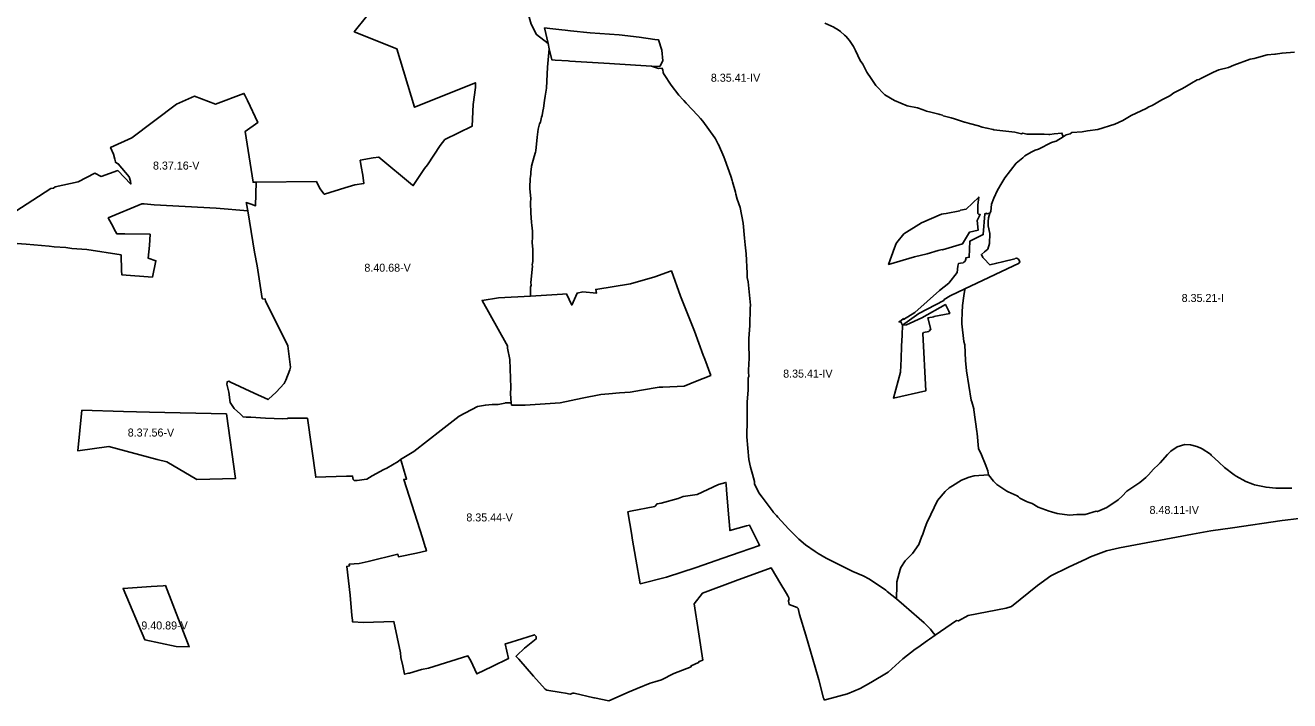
# Model space of a CAD drawing. Extents: x -444937 to -440470, y -1149084 to -1129741.
# Drawn here: x -443286 to -441707, y -1132883 to -1132039 of the extents above; entities that cross this region are included whole.
import ezdxf

# ---------------------------------------------------------------- set-up
doc = ezdxf.new("R2010")
doc.units = 0
doc.layers.add('Vrstva 28', color=7, linetype='Continuous')

msp = doc.modelspace()

# ---------------------------------------------------------------- linework, layer by layer
at = {"layer": 'Vrstva 28'}
for points in [[(-442663.04, -1132002.17), (-442658.9, -1132020.83), (-442654.27, -1132037.04), (-442647.66, -1132050.27), (-442633.17, -1132061.48)], [(-442998.03, -1132234.73), (-442922.59, -1132233.93), (-442918.4, -1132242.63), (-442912.99, -1132249.51), (-442912.72, -1132249.43), (-442887.05, -1132241.64), (-442874.77, -1132237.91), (-442863.26, -1132236.08), (-442864.88, -1132225.96), (-442866.63, -1132214.97), (-442867.88, -1132207.12), (-442851.91, -1132204.38), (-442844.71, -1132203.15), (-442802.61, -1132238.12), (-442801.77, -1132238.8), (-442787.72, -1132217.54), (-442783.89, -1132212.86), (-442767.92, -1132188.8), (-442762.18, -1132181.35), (-442727.93, -1132164.44), (-442726.84, -1132137.72), (-442724.07, -1132116.43), (-442724.07, -1132110.89), (-442724.04, -1132110.37), (-442800.21, -1132140.96), (-442822.05, -1132068.1), (-442875.47, -1132046.72), (-442860.07, -1132027.41)], [(-441989.7, -1132178.08), (-441991.21, -1132173.35), (-442001.18, -1132174.32), (-442006.51, -1132174.84), (-442007.71, -1132174.82), (-442013.34, -1132174.74), (-442019.94, -1132174.64), (-442034.98, -1132174.41), (-442040.09, -1132173.56), (-442041.79, -1132173.99), (-442050.29, -1132172.07), (-442076.22, -1132169.1), (-442077.21, -1132168.87), (-442084.99, -1132167.09), (-442091.1, -1132165.7), (-442095.35, -1132164), (-442106.74, -1132161.08), (-442112.78, -1132159.53), (-442112.89, -1132159.5), (-442119.3, -1132157.41), (-442125.37, -1132155.44), (-442129.78, -1132154.01), (-442139.56, -1132151.88), (-442139.71, -1132151.73), (-442140.41, -1132151.03), (-442143.81, -1132149.97), (-442144.91, -1132149.7), (-442154.88, -1132147.27), (-442160.39, -1132145.93), (-442164.78, -1132144.39), (-442171.86, -1132141.89), (-442184.61, -1132139.13), (-442200.34, -1132132.54), (-442212.67, -1132125.53), (-442223.93, -1132113.84), (-442229.73, -1132105.19), (-442235.2, -1132097.05), (-442240.09, -1132087.27), (-442243.28, -1132082.6), (-442249.2, -1132070.14), (-442250.91, -1132066.54), (-442251.56, -1132065.17), (-442256.66, -1132057.52), (-442261.13, -1132052.2), (-442262.73, -1132050.8), (-442267.93, -1132046.25), (-442270.93, -1132044.31), (-442275.79, -1132041.15), (-442276.39, -1132040.9), (-442287.7, -1132036.05)], [(-442633.17, -1132061.48), (-442637.57, -1132041.89), (-442631.25, -1132042.56), (-442615.94, -1132044.17), (-442612.11, -1132044.57), (-442605.25, -1132045.29), (-442580.6, -1132047.89), (-442544.42, -1132050.65), (-442519.3, -1132053.43), (-442500, -1132056.18), (-442495.39, -1132056.67), (-442491.09, -1132069.84), (-442490.03, -1132083.02), (-442493.22, -1132089.4), (-442493.79, -1132090.23), (-442503.89, -1132089.6)], [(-442631.7, -1132068.05), (-442633.8, -1132091.01), (-442635.31, -1132117.17), (-442636.82, -1132127.28), (-442637.6, -1132132.55), (-442639, -1132141.92), (-442639.77, -1132145.76), (-442640.85, -1132151.08), (-442641.33, -1132153.43), (-442642.55, -1132159.43), (-442644.04, -1132161.56), (-442645.53, -1132168.37), (-442646.7, -1132178.38), (-442648.72, -1132195.61), (-442649.14, -1132197.15), (-442650.65, -1132202.7), (-442653.85, -1132214.49), (-442654.04, -1132215.2), (-442654.62, -1132222.14), (-442654.79, -1132224.19), (-442655.11, -1132227.97), (-442655.75, -1132229.67), (-442656.14, -1132241.49), (-442656.17, -1132242.44), (-442654.89, -1132255.22), (-442655.32, -1132259.47), (-442655.3, -1132259.89), (-442654.63, -1132273.26), (-442654.35, -1132278.9), (-442654.04, -1132285.02), (-442653.56, -1132288.49), (-442652.55, -1132295.66), (-442652.78, -1132303.29), (-442652.98, -1132310.13), (-442652.22, -1132318.53), (-442652.13, -1132319.5), (-442652.34, -1132333.55), (-442652.98, -1132337.81), (-442652.55, -1132339.51), (-442654.89, -1132359.94), (-442654.47, -1132363.35), (-442655.11, -1132365.9), (-442655.05, -1132374.2), (-442655.03, -1132376.85)], [(-442631.7, -1132068.05), (-442633.17, -1132061.48)], [(-442550.17, -1132086.71), (-442556.66, -1132086.31), (-442606.22, -1132083.21), (-442608.28, -1132083.01), (-442624.45, -1132081.95), (-442624.57, -1132081.94), (-442628.65, -1132081.67), (-442631.33, -1132069.69), (-442631.7, -1132068.05)], [(-442503.89, -1132089.6), (-442550.17, -1132086.71)], [(-441989.7, -1132178.08), (-441986.1, -1132175.26), (-441981, -1132173.99), (-441978.88, -1132172.71), (-441966.13, -1132171.65), (-441959.43, -1132170.63), (-441946.57, -1132168.67), (-441925.32, -1132162.08), (-441915.12, -1132157.62), (-441904.92, -1132151.46), (-441886.15, -1132142.44), (-441882.81, -1132140.41), (-441878.56, -1132138.92), (-441866.66, -1132131.69), (-441856.46, -1132126.59), (-441851.36, -1132122.98), (-441850.48, -1132122.53), (-441841.53, -1132117.91), (-441837.75, -1132115.96), (-441829.47, -1132111.02), (-441822.45, -1132106.82), (-441819.9, -1132106.19), (-441818.59, -1132105.53), (-441802.05, -1132097.26), (-441801.87, -1132097.18), (-441795.25, -1132094.29), (-441783.35, -1132091.1), (-441776.47, -1132088.52), (-441756.14, -1132080.9), (-441751.04, -1132080.05), (-441748.41, -1132079.28), (-441734.89, -1132075.37), (-441725.47, -1132074.78), (-441724.69, -1132074.73), (-441716.18, -1132073.25), (-441700.78, -1132072.28)], [(-442197.83, -1132755.26), (-442209.51, -1132745.94), (-442211.39, -1132744.43), (-442231.59, -1132730.83), (-442239.45, -1132726.58), (-442252.63, -1132721), (-442256.03, -1132719.57), (-442285.78, -1132704.27), (-442295.98, -1132698.53), (-442299.44, -1132696.19), (-442311.71, -1132687.9), (-442320, -1132680.67), (-442325.01, -1132675.66), (-442332.96, -1132667.71), (-442346.21, -1132653.14), (-442348.08, -1132651.08), (-442351.65, -1132647.16), (-442352.09, -1132646.67), (-442365.97, -1132628.22), (-442370.16, -1132622.65), (-442375.26, -1132611.39), (-442375.47, -1132608.41), (-442377.98, -1132599.64), (-442380.57, -1132590.56), (-442382.49, -1132581.21), (-442384.82, -1132552.94), (-442384.62, -1132531.64), (-442384.57, -1132527), (-442384.42, -1132511.28), (-442384.4, -1132508.94), (-442383.34, -1132494.49), (-442383.34, -1132493.39), (-442383.34, -1132479.19), (-442383.23, -1132478.99), (-442382.49, -1132477.49), (-442382.91, -1132471.54), (-442382.34, -1132459.99), (-442382.17, -1132456.43), (-442381.85, -1132449.86), (-442382.49, -1132441.36), (-442382.27, -1132429.88), (-442381.3, -1132413.72), (-442380.68, -1132391.93), (-442380.57, -1132388.22), (-442383.34, -1132359.32), (-442384.4, -1132353.58), (-442384.66, -1132348.37), (-442385.89, -1132324.04), (-442386.94, -1132312.88), (-442387.71, -1132304.72), (-442389.5, -1132285.78), (-442393.32, -1132266.23), (-442396.94, -1132255.81), (-442398.57, -1132249.67), (-442399.32, -1132246.87), (-442402.74, -1132233.99), (-442403.1, -1132232.65), (-442405.15, -1132226.96), (-442412.58, -1132206.29), (-442413.73, -1132203.1), (-442420.32, -1132187.59), (-442420.59, -1132187.06), (-442423.61, -1132181.32), (-442424, -1132180.57), (-442424.78, -1132179.09), (-442439.87, -1132158.26), (-442442.79, -1132155.12), (-442446.37, -1132151.25), (-442460.6, -1132135.91), (-442463.6, -1132132.68), (-442464.46, -1132131.75), (-442469.84, -1132125.95), (-442479.62, -1132113.41), (-442488.33, -1132100.02), (-442489.39, -1132097.9), (-442490.03, -1132093.65), (-442491.09, -1132092.8), (-442490.67, -1132092.16), (-442495.43, -1132092.59), (-442503.89, -1132089.6)], [(-443306.47, -1132276.08), (-443254.53, -1132242.66), (-443251.08, -1132241.87), (-443248.93, -1132240.39), (-443220.48, -1132234.33), (-443199.49, -1132223.43), (-443191.66, -1132227.44), (-443170.95, -1132220.13), (-443154.66, -1132237.05), (-443155.12, -1132233.5), (-443156.48, -1132228.09), (-443170.32, -1132211.47), (-443170.87, -1132211.58), (-443173.77, -1132209.74), (-443173.84, -1132209.35), (-443174.49, -1132205.83), (-443176.37, -1132199.56), (-443179.84, -1132191.22), (-443153.2, -1132179.22), (-443097.29, -1132137.11), (-443075.14, -1132127.27), (-443048.69, -1132137.11), (-443013.18, -1132123.63), (-443012.08, -1132125.93), (-443008.86, -1132132.65)], [(-443008.86, -1132132.65), (-442995.8, -1132159.87), (-443011.58, -1132171.26), (-443001.87, -1132234.77), (-442998.03, -1132234.73)], [(-442081.7, -1132273.49), (-442080.99, -1132272.52), (-442080.05, -1132271.33), (-442079.2, -1132262.19), (-442076.43, -1132254.54), (-442071.76, -1132244.76), (-442066.35, -1132235.45), (-442062.62, -1132229.03), (-442048.59, -1132210.97), (-442040.34, -1132204.15), (-442037.54, -1132201.83), (-442029.89, -1132197.15), (-442024.79, -1132194.6), (-442020.54, -1132193.33), (-442004.38, -1132185.04), (-442003.24, -1132184.71), (-441998.43, -1132183.34), (-441989.7, -1132178.08)], [(-442998.03, -1132234.73), (-442998.63, -1132263.95), (-443004.32, -1132262.08), (-443010.39, -1132260.09), (-443010.04, -1132261.83), (-443008.35, -1132270.24)], [(-442145.93, -1132320), (-442159.54, -1132324.25), (-442175.69, -1132328.08), (-442207.83, -1132337.32), (-442200.33, -1132316.57), (-442198.44, -1132311.31), (-442197.5, -1132310.13), (-442188.9, -1132299.28), (-442166.69, -1132285.36), (-442141.8, -1132274.69), (-442139.09, -1132274.11), (-442135.73, -1132273.67), (-442118.94, -1132270.48), (-442118.14, -1132269.64), (-442110.98, -1132268.11), (-442095.21, -1132253.18), (-442096.41, -1132262.83), (-442096.27, -1132270.13), (-442096.2, -1132273.88), (-442095.14, -1132274.94), (-442093.32, -1132275.06), (-442097.06, -1132282.55), (-442095.83, -1132294.53), (-442106.83, -1132297.15), (-442115.37, -1132311.62), (-442115.66, -1132311.73)], [(-443008.35, -1132270.24), (-443048.05, -1132266.92), (-443125.53, -1132263.09), (-443137.67, -1132261.6), (-443140.86, -1132261.81), (-443182.84, -1132279.2), (-443178.75, -1132286.72), (-443173.64, -1132296.09), (-443171.87, -1132299.21), (-443161.9, -1132299.32), (-443130.57, -1132299.65), (-443131.31, -1132313.51), (-443132.73, -1132329.58), (-443123.2, -1132332.86), (-443127.65, -1132353.28), (-443165.86, -1132350.2), (-443166.05, -1132344.95), (-443166.73, -1132325.53), (-443209.4, -1132318.86), (-443228.13, -1132317.58), (-443235.77, -1132316.31), (-443235.8, -1132316.31), (-443235.88, -1132316.3), (-443250.27, -1132315.46), (-443256.38, -1132314.58), (-443285.39, -1132312.15), (-443313.66, -1132309.79)], [(-442817.55, -1132581.15), (-442820.71, -1132583.45), (-442834.76, -1132591.75), (-442838.44, -1132593.68), (-442853.07, -1132601.33), (-442859.88, -1132605.8), (-442860.14, -1132605.83), (-442871.59, -1132607.36), (-442872.65, -1132607.5), (-442875.63, -1132607.29), (-442876.81, -1132606.11), (-442876.91, -1132606.01), (-442877.41, -1132601.88), (-442884.98, -1132602.11), (-442897.86, -1132602.5), (-442910.8, -1132602.89), (-442923.51, -1132603.27), (-442933.87, -1132529.67), (-442957.8, -1132529.6), (-442958.85, -1132529.73), (-442964.61, -1132530.45), (-442986.16, -1132529.34), (-443004.72, -1132528.38), (-443010.22, -1132528.1), (-443010.6, -1132528.08), (-443014.21, -1132527.89), (-443017.7, -1132524.66), (-443025.49, -1132517.46), (-443030.6, -1132509.8), (-443032.3, -1132497.03), (-443034.64, -1132487.02), (-443034.18, -1132484.88), (-443034, -1132484.04), (-443032.09, -1132483.4), (-443030.17, -1132484.31), (-443000.39, -1132498.34), (-442983.08, -1132506.27), (-442982.61, -1132505.84), (-442972.91, -1132497.03), (-442962.91, -1132486.17), (-442960.78, -1132482.13), (-442956.05, -1132469.09), (-442954.88, -1132465.87), (-442958.54, -1132439.22), (-442986.29, -1132382.77), (-442986.67, -1132380.75), (-442989.74, -1132380.23), (-442990.2, -1132380.16), (-442990.25, -1132379.86), (-442996.54, -1132339.08), (-442999.94, -1132322.05), (-443008.35, -1132270.24)], [(-442190.46, -1132413.21), (-442192.39, -1132409.19), (-442194.9, -1132409.23), (-442192.76, -1132407.65), (-442189.32, -1132405.12), (-442189.16, -1132406.16), (-442174.91, -1132397.52), (-442144.09, -1132369.96), (-442132.77, -1132360.59), (-442122.05, -1132347.42), (-442121.19, -1132339.4), (-442120.72, -1132336.22), (-442117.98, -1132335.81), (-442114.48, -1132335.3), (-442113.79, -1132334.61), (-442112.35, -1132333.18), (-442111.5, -1132330.84), (-442111.4, -1132329.32), (-442107.06, -1132328.34), (-442106.41, -1132308.36), (-442089.68, -1132300.03), (-442087.82, -1132274.16), (-442085, -1132273.48), (-442085.05, -1132274.25), (-442081.7, -1132273.49)], [(-442081.7, -1132273.49), (-442081.27, -1132273.4), (-442083.02, -1132278.98), (-442083.45, -1132283.87), (-442083.45, -1132289.18), (-442081.53, -1132298.53), (-442081.96, -1132311.29), (-442083.87, -1132318.09), (-442088.15, -1132321.69), (-442091.95, -1132324.89), (-442090.04, -1132328.71), (-442088.93, -1132329.88), (-442081.36, -1132337.86), (-442072.75, -1132335.74), (-442072.69, -1132335.79), (-442065.44, -1132333.93), (-442050.29, -1132330.2), (-442049.58, -1132329.88), (-442047.64, -1132329.38), (-442045.19, -1132331.26), (-442043.91, -1132334.03), (-442044.62, -1132335.43), (-442044.76, -1132335.73), (-442112.61, -1132368.06)], [(-442115.66, -1132311.73), (-442140.41, -1132319.15), (-442141.04, -1132318.72), (-442145.93, -1132320)], [(-442655.03, -1132376.85), (-442615.16, -1132374.5), (-442610.35, -1132374.22), (-442603.76, -1132388.16), (-442597.06, -1132373.13), (-442589.82, -1132371.73), (-442572.97, -1132373.39), (-442573.66, -1132368.62), (-442530.37, -1132361.65), (-442500, -1132352.91), (-442480.46, -1132345.93), (-442479.18, -1132345.49), (-442467.93, -1132376.96), (-442450.5, -1132420.95), (-442439.34, -1132450.86), (-442437.46, -1132455.89), (-442429.98, -1132475.95), (-442448.94, -1132483.63), (-442449.01, -1132483.65), (-442449.12, -1132483.71), (-442463.1, -1132489.37), (-442489.71, -1132490.59), (-442494.3, -1132490.8), (-442516.66, -1132494.48), (-442530.83, -1132496.81), (-442543.89, -1132497.93), (-442557.53, -1132498.98), (-442567.27, -1132499.73), (-442590.58, -1132504.43), (-442618.29, -1132510.35), (-442661.74, -1132513.33), (-442667.45, -1132513.26), (-442678.99, -1132513.12)], [(-442112.61, -1132368.06), (-442131.06, -1132376.75), (-442138.49, -1132381.21), (-442138.89, -1132382.4), (-442170.2, -1132398.89), (-442190.46, -1132413.21)], [(-442082.88, -1132600.42), (-442083.87, -1132595.23), (-442086.21, -1132588.43), (-442091.89, -1132575.21), (-442095.35, -1132567.18), (-442097.21, -1132548.54), (-442097.47, -1132545.93), (-442101.35, -1132519.02), (-442101.51, -1132517.87), (-442103.84, -1132509.22), (-442104.49, -1132506.82), (-442110.65, -1132470.26), (-442111.93, -1132457.51), (-442112.78, -1132437.96), (-442113.84, -1132433.71), (-442116.39, -1132411.6), (-442116.23, -1132408.23), (-442115.73, -1132397.43), (-442115.33, -1132388.65), (-442113.74, -1132376.62), (-442112.7, -1132368.79), (-442112.61, -1132368.06)], [(-442679.3, -1132510.41), (-442680.06, -1132499.18), (-442679.61, -1132491.35), (-442680.87, -1132456.05), (-442683.81, -1132442.18), (-442683.9, -1132442.07), (-442684.09, -1132439.27), (-442685.74, -1132436.3), (-442715.8, -1132382.41), (-442695.34, -1132379.1), (-442655.03, -1132376.85)], [(-442190.46, -1132413.21), (-442185.39, -1132412.76), (-442166.39, -1132404.06), (-442136.9, -1132387.58), (-442132.76, -1132395.88), (-442131.45, -1132398.48), (-442151.13, -1132402.4), (-442151.06, -1132402.72), (-442158.66, -1132404.3), (-442155, -1132418.65), (-442155.39, -1132419.06), (-442156.75, -1132419.42), (-442156.68, -1132420.41), (-442157.41, -1132421.17), (-442164.21, -1132422.23), (-442165.27, -1132423.72), (-442161.52, -1132495.46), (-442201.84, -1132504.34), (-442192.94, -1132471.9), (-442192.24, -1132455.49), (-442191.56, -1132439.42), (-442190.99, -1132425.84), (-442190.46, -1132413.21)], [(-442679.3, -1132510.41), (-442686.79, -1132510.3), (-442687.16, -1132510.68), (-442695.54, -1132512.36), (-442702.95, -1132512.57), (-442711.52, -1132513.04), (-442721.42, -1132514.88), (-442744.39, -1132527.16), (-442767.01, -1132544.62), (-442800.83, -1132571.12), (-442817.55, -1132581.15)], [(-442678.99, -1132513.12), (-442679.3, -1132510.41)], [(-443034.86, -1132524.23), (-443023.57, -1132604.76), (-443072.22, -1132605.91), (-443109.66, -1132584.16), (-443121.77, -1132580.95), (-443181.92, -1132564.99), (-443220.84, -1132570.16), (-443215.95, -1132519.46)], [(-443215.95, -1132519.46), (-443163.72, -1132521.23), (-443131.19, -1132521.82), (-443034.86, -1132524.23)], [(-441704.25, -1132617.13), (-441724.26, -1132617.13), (-441736.16, -1132615.85), (-441750.62, -1132612.66), (-441752.91, -1132611.78), (-441761.67, -1132608.41), (-441773.56, -1132601.76), (-441776.12, -1132600.34), (-441788.23, -1132590.98), (-441795.07, -1132584.64), (-441804.83, -1132575.58), (-441805.87, -1132574.62), (-441816.08, -1132567.82), (-441817.71, -1132567.1), (-441822.88, -1132564.84), (-441830.53, -1132562.72), (-441837.75, -1132562.5), (-441847.32, -1132565.48), (-441855.4, -1132570.58), (-441859.2, -1132574.88), (-441868.57, -1132585.46), (-441870.77, -1132587.43), (-441877.07, -1132593.11), (-441883.21, -1132600.09), (-441886.43, -1132603.74), (-441894.08, -1132609.9), (-441910.02, -1132620.74), (-441916.17, -1132626.77), (-441921.07, -1132631.58), (-441935.1, -1132641.14), (-441947, -1132646.24), (-441948.7, -1132645.82), (-441962.3, -1132649.64), (-441972.5, -1132649.64), (-441981.85, -1132650.49), (-441997.16, -1132648.58), (-442004.13, -1132646.69), (-442007.36, -1132645.82), (-442020.96, -1132640.5), (-442028.61, -1132636.25), (-442033.49, -1132634.42), (-442035.41, -1132633.7), (-442043.91, -1132629.24), (-442045.76, -1132627.86), (-442047.32, -1132626.69), (-442058.49, -1132621.47), (-442060.07, -1132620.74), (-442072.61, -1132612.45), (-442076.86, -1132608.2), (-442082.85, -1132600.46), (-442082.88, -1132600.42)], [(-442817.55, -1132581.15), (-442817.01, -1132582.94), (-442811.01, -1132602.59), (-442810.11, -1132605.52), (-442813.59, -1132605.91), (-442790.06, -1132678.81), (-442786.66, -1132690.31), (-442786.02, -1132692.44), (-442785.17, -1132695.33), (-442797.73, -1132698.18), (-442820.34, -1132702.72), (-442820.94, -1132699.45), (-442857.91, -1132708.5), (-442869.28, -1132711.26), (-442881.76, -1132711.8), (-442881.48, -1132714.12), (-442884.73, -1132714.65), (-442880.71, -1132750.67), (-442878.32, -1132776.06), (-442877.77, -1132781.86), (-442877.56, -1132784.14), (-442863.71, -1132784.6), (-442826.12, -1132783.48), (-442817.52, -1132822.71), (-442817.1, -1132828.67), (-442814.77, -1132839.12), (-442812.98, -1132847.2), (-442812.46, -1132849.51), (-442810.87, -1132849.1), (-442807.52, -1132848.25), (-442806.57, -1132847.96), (-442791.55, -1132843.36), (-442782.82, -1132841.65), (-442733.44, -1132826.64), (-442729.82, -1132832.71), (-442722.3, -1132848.94), (-442703, -1132839.61), (-442682.57, -1132829.73), (-442686.91, -1132811.63), (-442684.91, -1132811), (-442665.97, -1132805.07), (-442650.21, -1132800.14), (-442648.08, -1132802.48), (-442648.29, -1132805.25), (-442662.53, -1132816.91), (-442663.62, -1132817.81), (-442671.28, -1132825.05), (-442673.23, -1132826.89), (-442673.03, -1132827.13), (-442671.29, -1132829.1), (-442669.79, -1132830.8), (-442651.4, -1132851.69), (-442636.8, -1132868.26), (-442634.89, -1132869.32), (-442616.8, -1132872.39), (-442611.54, -1132873.26), (-442605.72, -1132874.22), (-442602.32, -1132872.94), (-442600.61, -1132873.16), (-442576.09, -1132878.88), (-442575.07, -1132879.12), (-442557.19, -1132882.52), (-442532.09, -1132871.45), (-442522.17, -1132867.08), (-442505.82, -1132860.52), (-442500, -1132858.77), (-442491.52, -1132856.23), (-442475.99, -1132848.61), (-442454.58, -1132840.14), (-442454.69, -1132838.89), (-442445.18, -1132834.76), (-442444.64, -1132833.48), (-442440.01, -1132831.69), (-442445.46, -1132796.62), (-442450.91, -1132761.54), (-442440.44, -1132748.14), (-442399.21, -1132732.88), (-442354.63, -1132716.39), (-442353.37, -1132718.5), (-442343.55, -1132734.93), (-442335.47, -1132748.39), (-442333.81, -1132751.48), (-442332.11, -1132754.64), (-442332.7, -1132757.78), (-442332.75, -1132758.04), (-442332.11, -1132762.29), (-442322.13, -1132765.9), (-442320.64, -1132767.39), (-442319.15, -1132774.83), (-442311.45, -1132800.71), (-442299.53, -1132840.74), (-442294.92, -1132856.23), (-442289.18, -1132879.18), (-442288.25, -1132880.31), (-442288.94, -1132880.21), (-442288.53, -1132881.89)], [(-442197.83, -1132755.26), (-442197.46, -1132738.06), (-442197.37, -1132733.81), (-442193.54, -1132718.5), (-442192.48, -1132715.96), (-442186.95, -1132707.88), (-442178.03, -1132698.53), (-442170.16, -1132687.47), (-442168.39, -1132682.75), (-442166.69, -1132678.23), (-442165.27, -1132674.42), (-442161.95, -1132665.58), (-442159.96, -1132660.27), (-442154.94, -1132649.75), (-442146.57, -1132632.22), (-442137.22, -1132621.16), (-442132.33, -1132616.7), (-442127.89, -1132613.94), (-442116.6, -1132606.92), (-442107.04, -1132603.1), (-442101.09, -1132601.61), (-442082.88, -1132600.42)], [(-442528.08, -1132679.35), (-442528.72, -1132675.48), (-442533.58, -1132646.35), (-442530.37, -1132645.82), (-442500, -1132639.88), (-442497.04, -1132636.47), (-442491.94, -1132635.83), (-442470.69, -1132629.67), (-442464.5, -1132627.26), (-442447.05, -1132625.05), (-442420.22, -1132612.49), (-442411.15, -1132609.73), (-442410.97, -1132612.24), (-442410.54, -1132618.83), (-442408.33, -1132644.42), (-442406.29, -1132668.13)], [(-441643.57, -1132648.43), (-441712.26, -1132656.77), (-441716.2, -1132657.25), (-441778.01, -1132666.33), (-441805.4, -1132670.35), (-441828.13, -1132674.57), (-441919.46, -1132691.53), (-441935.57, -1132695.4), (-441955.61, -1132702.82), (-441960.41, -1132705.15), (-441982.96, -1132715.44), (-442005.35, -1132726.68), (-442021.84, -1132738.53), (-442054.45, -1132764.64), (-442061.05, -1132766.96), (-442108.4, -1132776.19), (-442120.54, -1132782.76), (-442123.2, -1132782.3), (-442143.17, -1132796.2), (-442149.48, -1132800.59)], [(-442406.29, -1132668.13), (-442406.13, -1132670), (-442385.25, -1132664.1), (-442381.81, -1132663.12), (-442381.33, -1132664.08), (-442369.95, -1132686.62), (-442368.95, -1132688.6), (-442393.11, -1132697.09), (-442415.1, -1132704.47), (-442448.4, -1132716.13), (-442485.12, -1132728.02), (-442518.05, -1132736.28), (-442523.43, -1132705.73), (-442528.08, -1132679.35)], [(-443097.71, -1132814.64), (-443137.18, -1132806.31), (-443164.19, -1132742.19), (-443129.3, -1132739.84), (-443114.32, -1132738.93), (-443111.33, -1132738.6)], [(-443111.33, -1132738.6), (-443081.79, -1132815.25), (-443097.71, -1132814.64)], [(-442149.48, -1132800.59), (-442149.52, -1132800.54), (-442153.22, -1132795.94), (-442155.5, -1132793.11), (-442163.57, -1132785.24), (-442169.57, -1132779.99), (-442188.76, -1132763.2), (-442197.83, -1132755.26)], [(-442149.48, -1132800.59), (-442156.63, -1132805.56), (-442159.31, -1132807.43), (-442171.4, -1132815.84), (-442174.62, -1132818.08), (-442189.88, -1132830.09), (-442208.28, -1132846.89), (-442230.21, -1132859.87), (-442243.38, -1132867.08), (-442259.11, -1132873.83), (-442285.23, -1132881.09), (-442288.53, -1132881.89)]]:
    msp.add_lwpolyline(points, dxfattribs=at)

# ---------------------------------------------------------------- texts
for s, p in [('8.35.41-IV', (-442429.89, -1132109.09)), ('8.37.16-V', (-443126.85, -1132218.84)), ('8.40.68-V', (-442862.76, -1132346.48)), ('8.35.21-I', (-441841.72, -1132384.26)), ('8.35.41-IV', (-442339.55, -1132478.78)), ('8.37.56-V', (-443158.41, -1132552.4)), ('8.48.11-IV', (-441881.84, -1132649.14)), ('8.35.44-V', (-442735.34, -1132658.5)), ('9.40.89-V', (-443141.4, -1132793.48))]:
    msp.add_text(s, height=10, dxfattribs=at).set_placement(p)

doc.saveas('drawing.dxf')
